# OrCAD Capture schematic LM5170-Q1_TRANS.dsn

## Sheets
1 PAGE1: size E; title: LM5170-Q1 Multiphase Bidirectional Current Controller; rev: 1.0; note: Datasheet: SNVSAQ6B    EVM: NA; note: Synchronous Step Down Converter
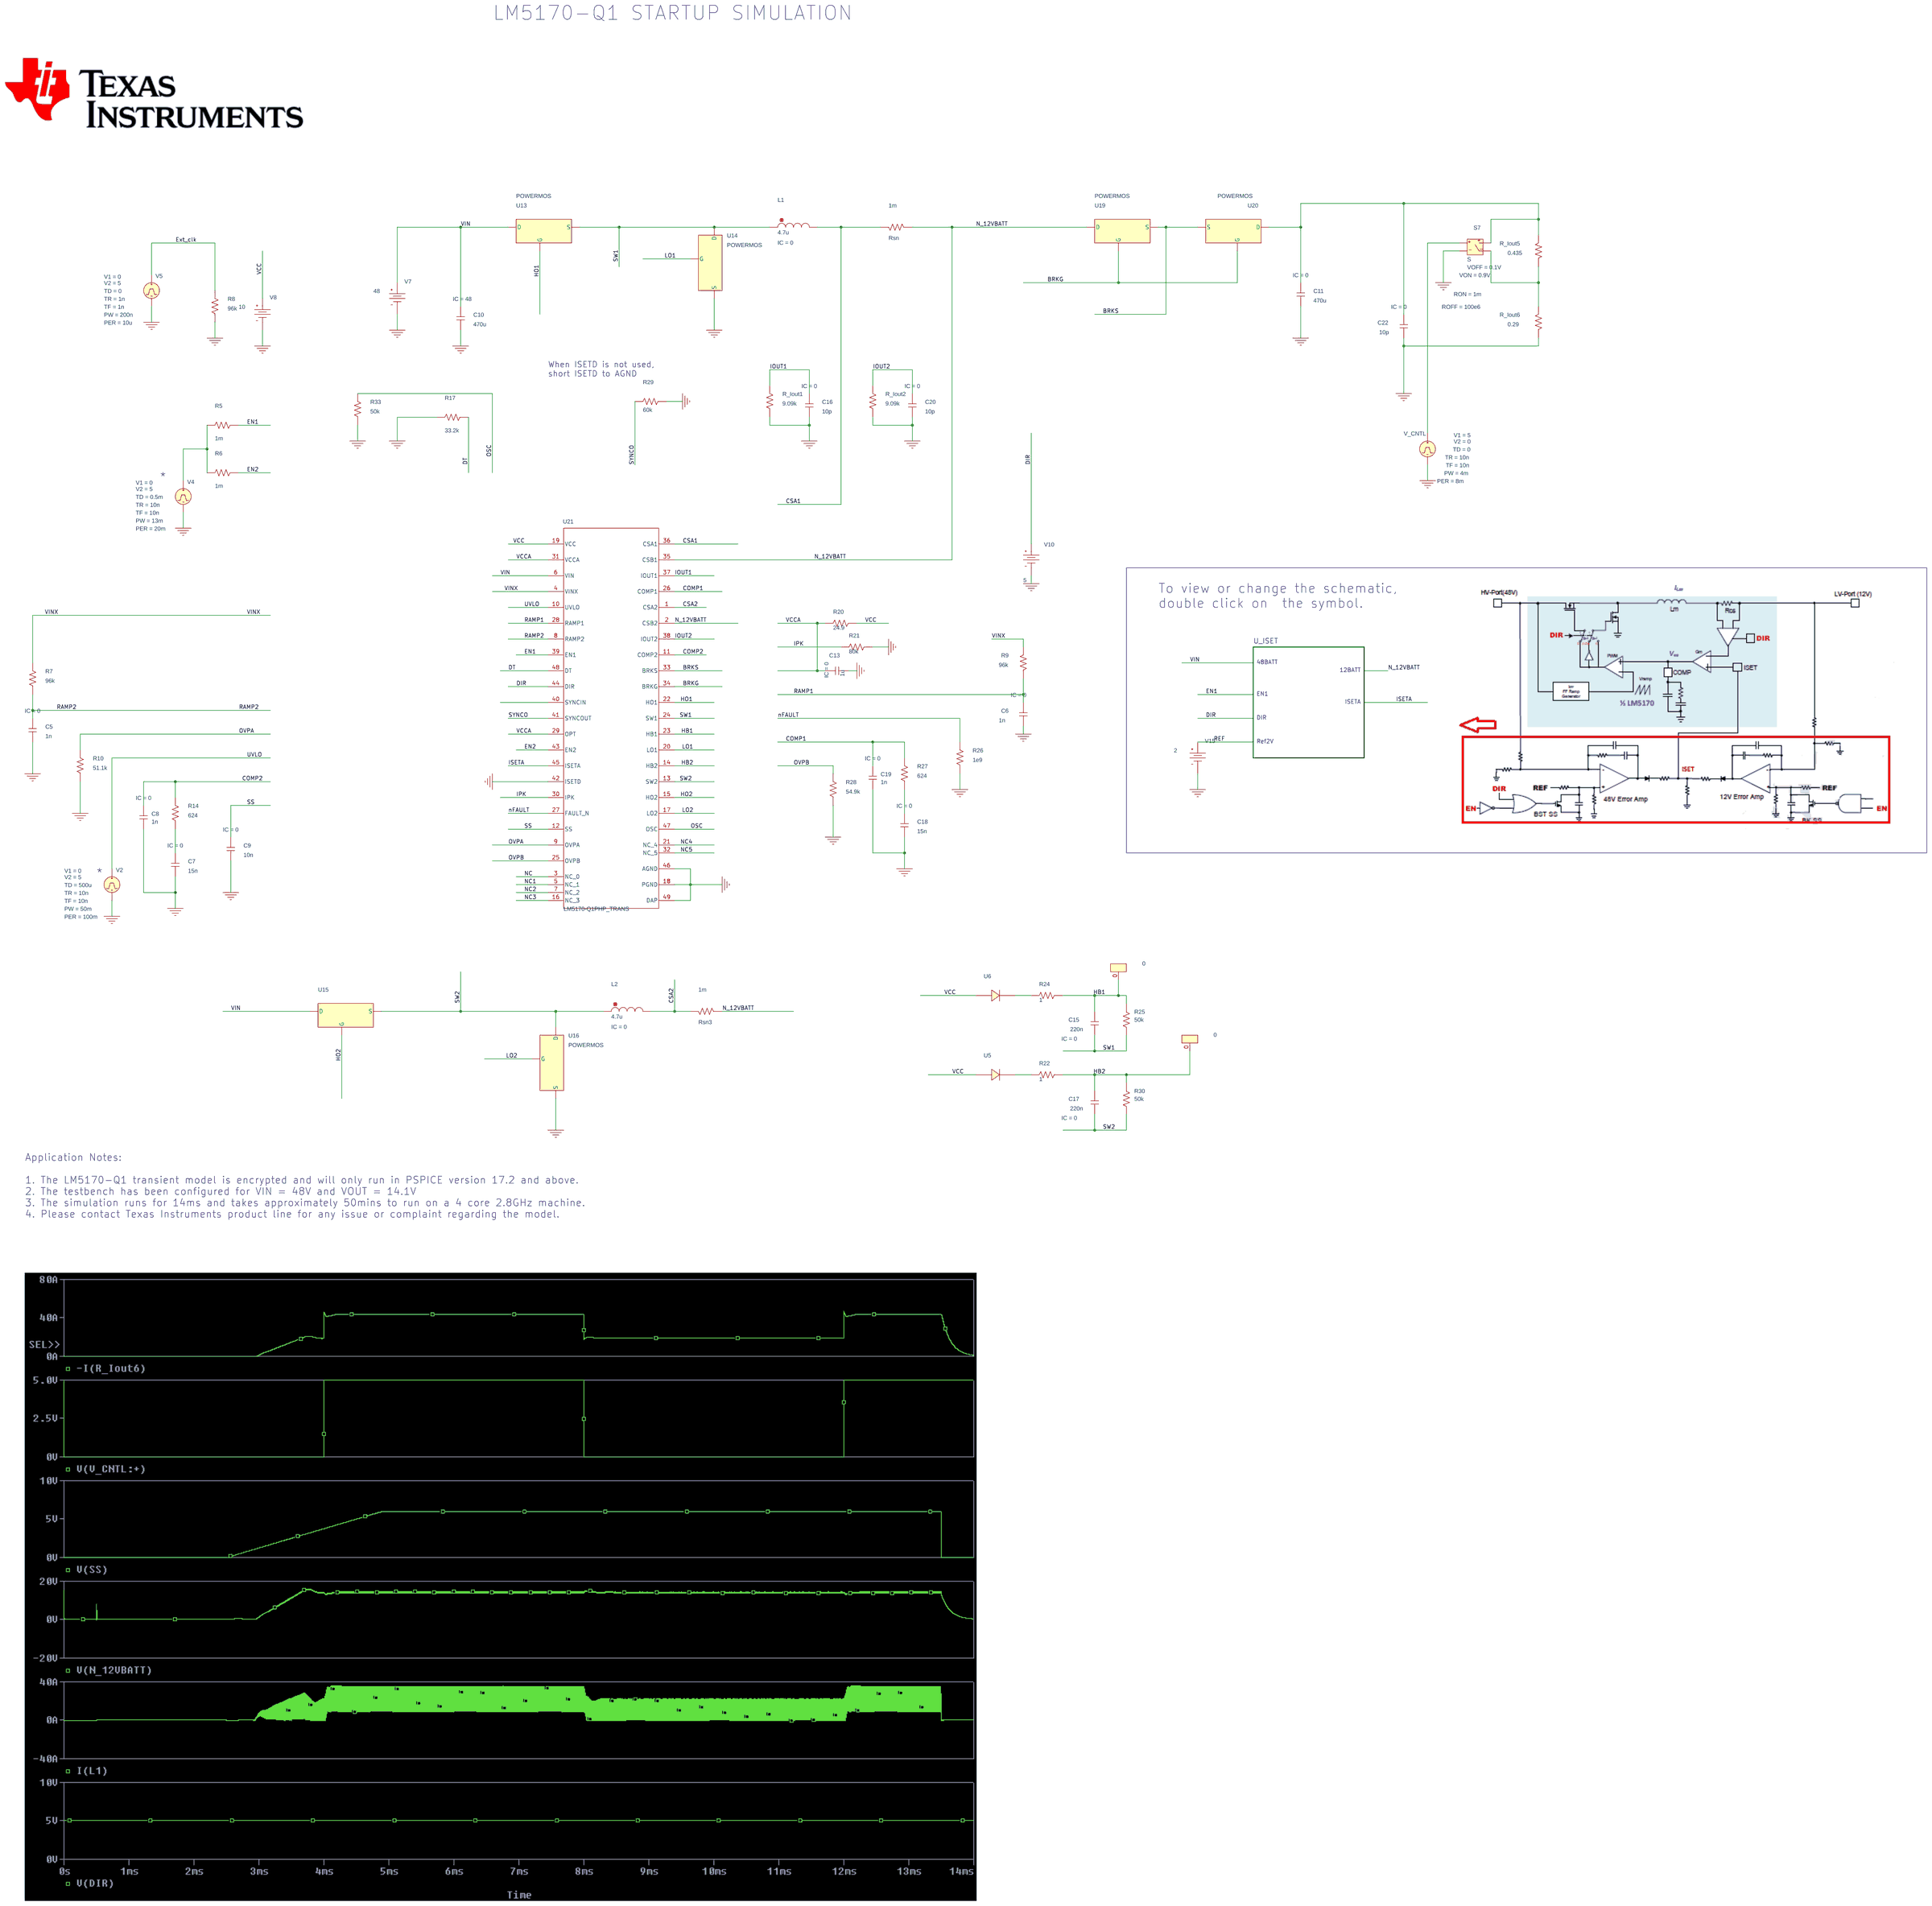
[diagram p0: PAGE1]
2 PAGE1 (2): size Custom; block U_ISET
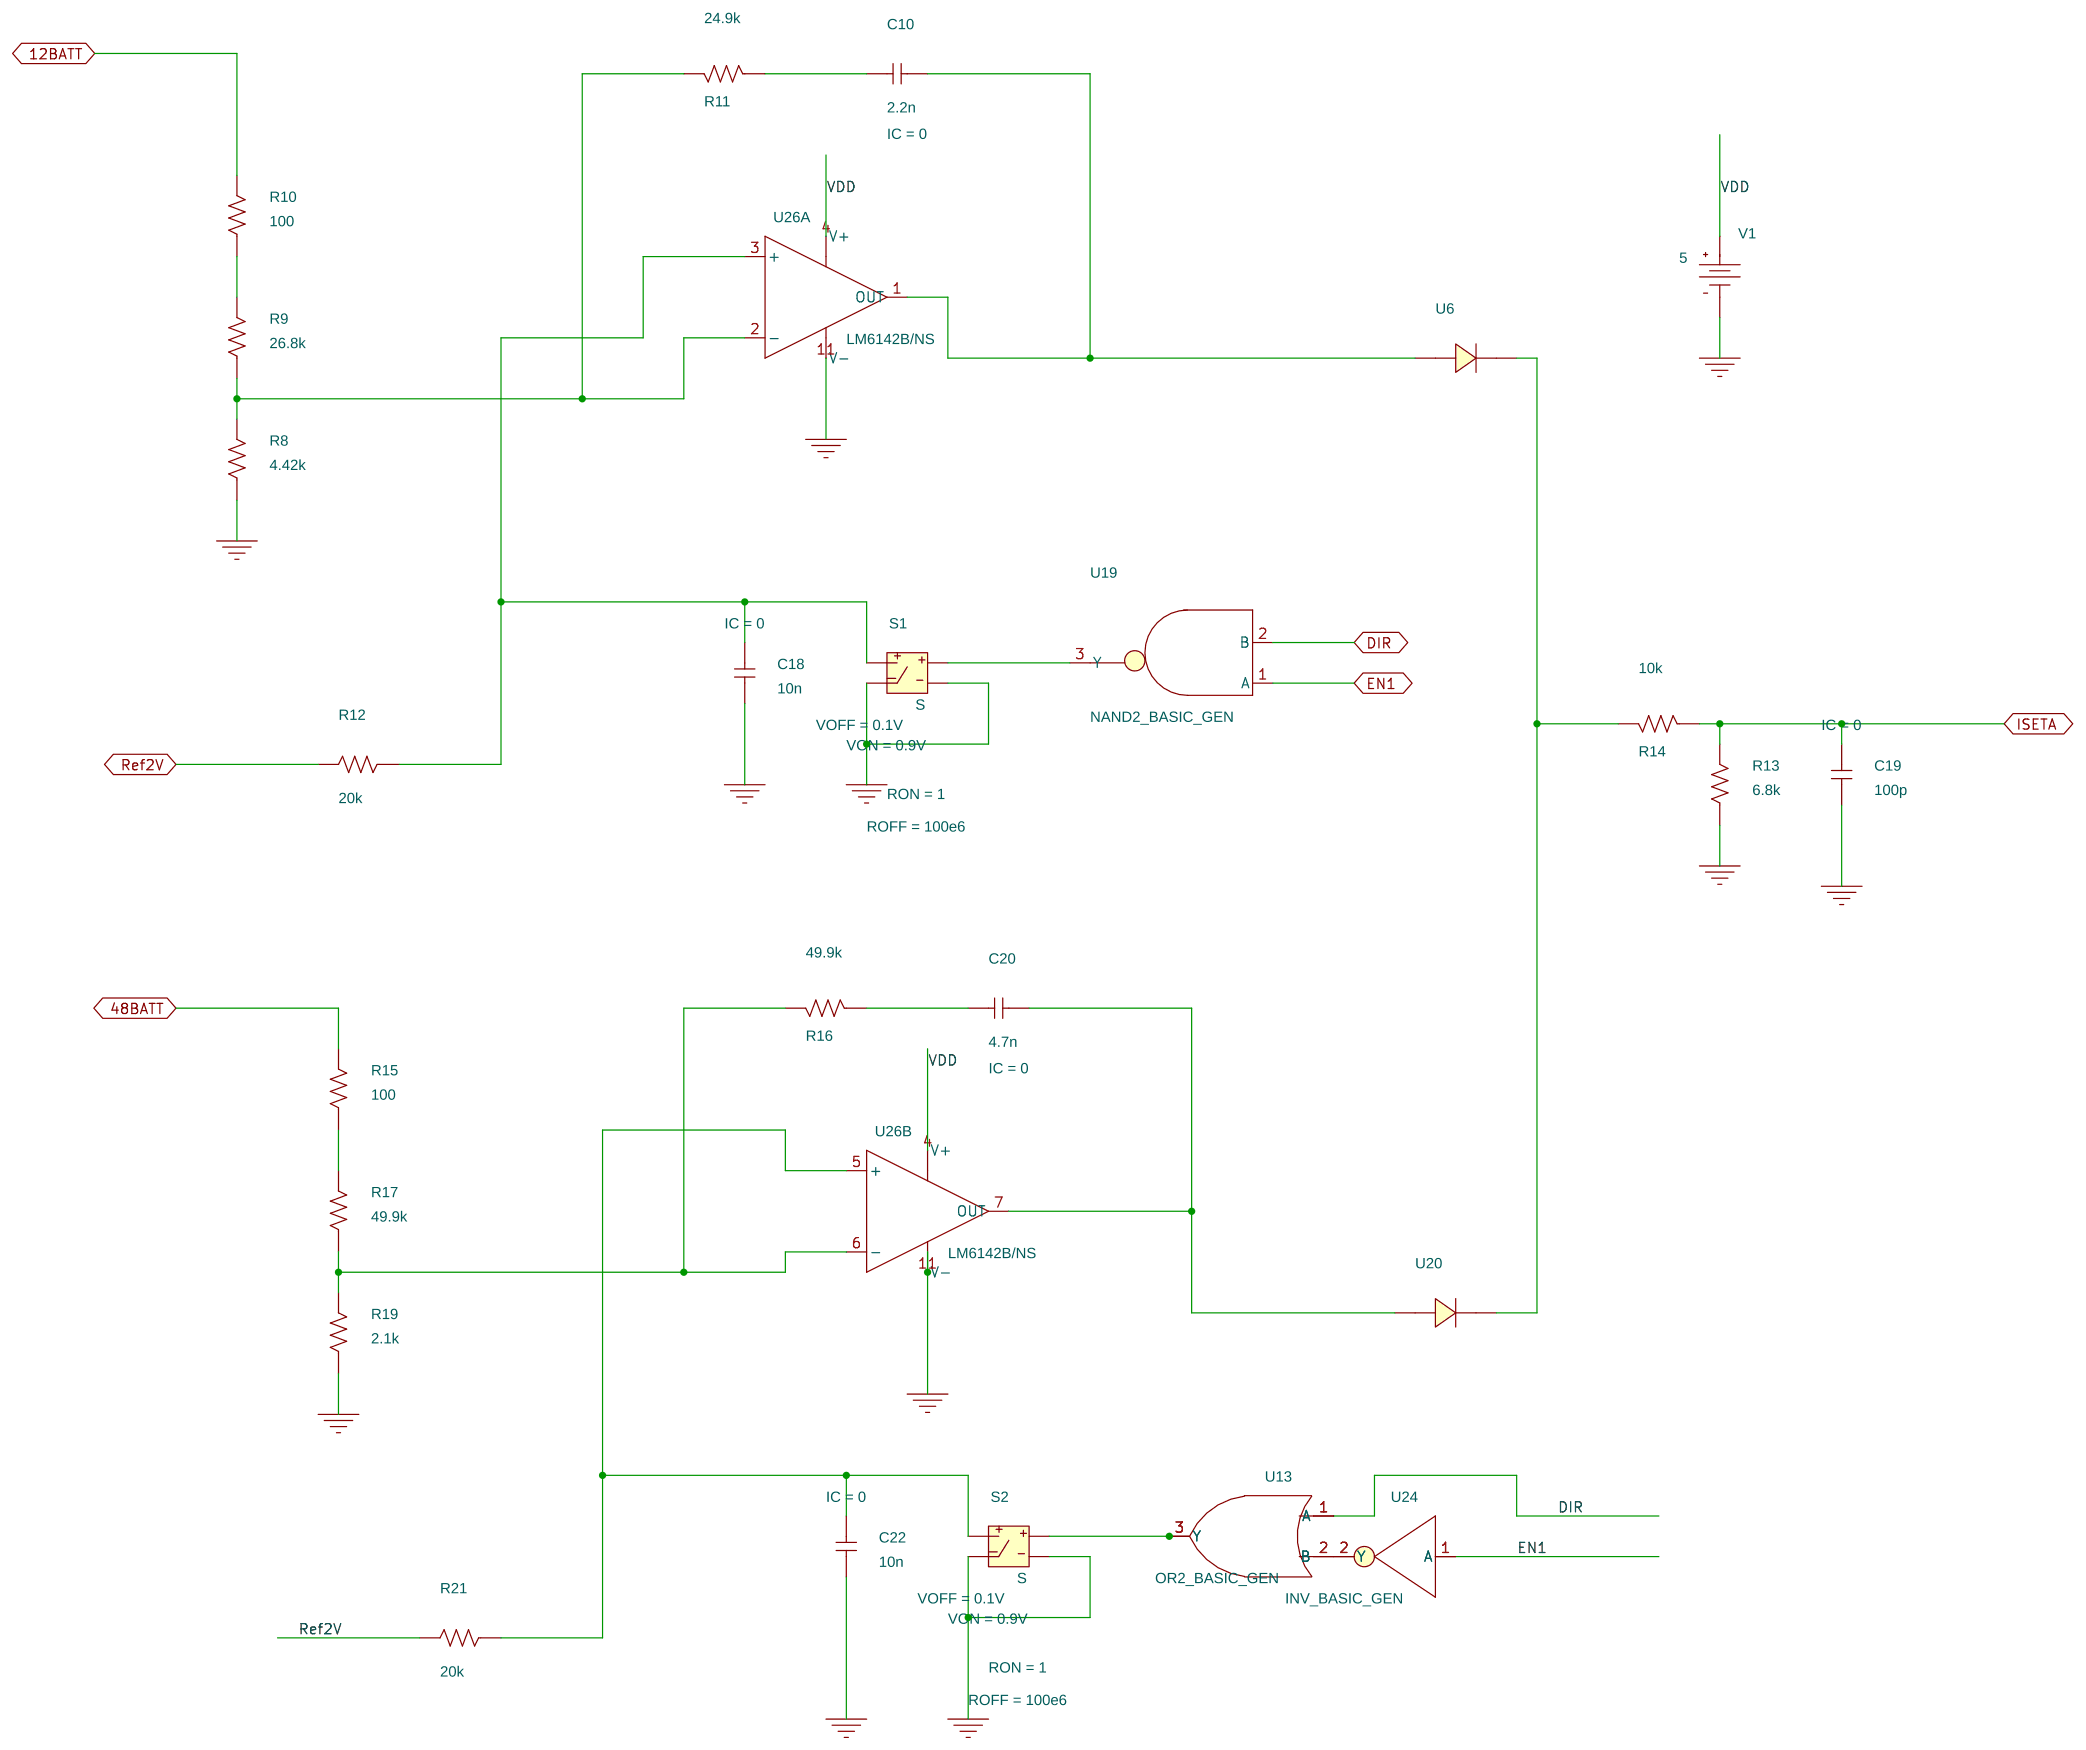
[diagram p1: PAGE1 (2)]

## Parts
sheet PAGE1 (2)
C10#2  2.2n  [RAD/CK05]
C18#2  10n  [RAD/CK05]
C19#2  100p  [RAD/CK05]
C20#2  4.7n  [RAD/CK05]
C22#2  10n  [RAD/CK05]
R8#2  4.42k  [AX/RC05]
R9#2  26.8k  [AX/RC05]
R10#2  100  [AX/RC05]
R11  24.9k  [AX/RC05]
R12  20k  [AX/RC05]
R13  6.8k  [AX/RC05]
R14#2  10k  [AX/RC05]
R15  100  [AX/RC05]
R16  49.9k  [AX/RC05]
R17#2  49.9k  [AX/RC05]
R19  2.1k  [AX/RC05]
R21#2  20k  [AX/RC05]
S1  S
S2  S
U6#2  D_D
U24  INV_BASIC_GEN
U26  LM6142B/NS  [DIP1008W300L450]  (sections A,B)
V1  VDC
sheet PAGE1
C5  1n  [RAD/CK05]
C6  1n  [RAD/CK05]
C7  15n  [RAD/CK05]
C8  1n  [RAD/CK05]
C9  10n  [RAD/CK05]
C10  470u  [RAD/CK05]
C11  470u  [RAD/CK05]
C13  1u  [RAD/CK05]
C15  220n  [RAD/CK05]
C16  10p  [RAD/CK05]
C17  220n  [RAD/CK05]
C18  15n  [RAD/CK05]
C19  1n  [RAD/CK05]
C20  10p  [RAD/CK05]
C22  10p  [RAD/CK05]
IC1  0
IC2  0
L1  4.7u  [DISC/.350x.175/LS.200x.100/.034]
L2  4.7u  [DISC/.350x.175/LS.200x.100/.034]
R5  1m  [AX/RC05]
R6  1m  [AX/RC05]
R7  96k  [AX/RC05]
R8  96k  [AX/RC05]
R9  96k  [AX/RC05]
R10  51.1k  [AX/RC05]
R14  624  [AX/RC05]
R17  33.2k  [AX/RC05]
R20  24.9  [AX/RC05]
R21  80k  [AX/RC05]
R22  1  [AX/RC05]
R24  1  [AX/RC05]
R25  50k  [AX/RC05]
R26  1e9  [AX/RC05]
R27  624  [AX/RC05]
R28  54.9k  [AX/RC05]
R29  60k  [AX/RC05]
R30  50k  [AX/RC05]
R33  50k  [AX/RC05]
R_Iout1  9.09k  [AX/RC05]
R_Iout2  9.09k  [AX/RC05]
R_Iout5  0.435  [AX/RC05]
R_Iout6  0.29  [AX/RC05]
Rsn  1m  [AX/RC05]
Rsn3  1m  [AX/RC05]
S7  S
U5  D_D
U6  D_D
U13  POWERMOS
U14  POWERMOS
U15  POWERMOS
U16  POWERMOS
U19  POWERMOS
U20  POWERMOS
U21  LM5170-Q1PHP_TRANS  [PHP0048D_N]
V2  VPULSE
V4  VPULSE
V5  VPULSE
V7  VDC
V8  VDC
V10  VDC
V15  VDC
V_CNTL  VPULSE

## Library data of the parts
C5-C9 C10#2 C11 C13 C15-C18 C18#2 C19 C19#2 C20 C20#2 C22 C22#2 = C: IC: 0
R5-R8 R8#2 R9 R9#2 R10 R10#2 R11-R14 R14#2 R15-R17 R17#2 R19-R21 R21#2 R22 R24-R30 R33 R_Iout1 R_Iout2 R_Iout5 R_Iout6 Rsn Rsn3 = R
S1 S2 = S: ROFF: 100e6; RON: 1; VOFF: 0.1V; VON: 0.9V
U6 U6#2 = D_D
U24 = INV_BASIC_GEN
U26 = LM6142B_NS
V1 V10 = VDC: DC: 5
C10 = C: IC: 48
IC1 IC2 = IC1
L1 L2 = L: IC: 0
S7 = S: ROFF: 100e6; RON: 1m; VOFF: 0.1V; VON: 0.9V
U5 = D_D_1
U13 = POWERMOS_1_4
U14 = POWERMOS_1_2
U15 = POWERMOS_1_5
U16 = POWERMOS_1_1
U19 = POWERMOS_1
U20 = POWERMOS_1_3
U21 = LM5170-Q1PHP_TRANS
V2 = VPULSE: PER: 100m; PW: 50m; TD: 500u; TF: 10n; TR: 10n; V1: 0; V2: 5
V4 = VPULSE: PER: 20m; PW: 13m; TD: 0.5m; TF: 10n; TR: 10n; V1: 0; V2: 5
V5 = VPULSE: PER: 10u; PW: 200n; TD: 0; TF: 1n; TR: 1n; V1: 0; V2: 5
V7 = VDC: DC: 48
V8 = VDC: DC: 10
V15 = VDC: DC: 2
V_CNTL = VPULSE: PER: 8m; PW: 4m; TD: 0; TF: 10n; TR: 10n; V1: 5; V2: 0

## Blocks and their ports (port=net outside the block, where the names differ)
U_ISET = schematic Iset_driver_block, on sheet PAGE1: 12BATT=N_12VBATT, Ref2V=REF, DIR, EN1, ISETA, 48BATT=VIN

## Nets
U_ISET/VDD: U26.4(V+) V1.0(+)
VCC: R20.1 U5.1 U6.1 U21.19(VCC) V8.0(+)
VCCA: C13.2 R20.2 U21.29(OPT) U21.31(VCCA)
VIN: C10.2 R15.2 U13.D U15.D U21.6(VIN) V7.0(+)
VINX: R7.2 R9.2 U21.4(VINX)
0: C5.1 C6.1 C7.1 C8.1 C9.1 C10.1 C11.1 C13.1 C16.1 C18.1 C18#2.1 C19.1 C19#2.1 C20.1 C22.1 C22#2.1 R8.1 R8#2.1 R10.1 R13.1 R17.2 R19.1 R21.1 R26.1 R28.1 R29.1 R33.1 R_Iout1.1 R_Iout2.1 R_Iout6.1 S1.1(2) S1.3(4) S2.1(2) S2.3(4) S7.1(2) U14.S U16.S U21.18(PGND) U21.42(ISETD) U21.46(AGND) U21.49(DAP) U26.11(V-) V1.1(-) V2.2(-) V4.2(-) V5.2(-) V7.1(-) V8.1(-) V10.1(-) V15.1(-) V_CNTL.2(-)
BRKG: U19.G U20.G U21.34(BRKG)
BRKS: U19.S U20.S U21.33(BRKS)
COMP1: C19.2 R27.2 U21.26(COMP1)
COMP2: C8.2 R14.2 U21.11(COMP2)
CSA1: L1.2 Rsn.2 U21.36(CSA1)
CSA2: L2.2 Rsn3.2 U21.1(CSA2)
DIR: U13.1(A) U19.2(B) U21.44(DIR) V10.0(+)
DT: R17.1 U21.48(DT)
EN1: R5.1 U19.1(A) U21.39(EN1) U24.1(A)
EN2: R6.1 U21.43(EN2)
Ext_clk: R8.2 V5.1(+)
HB1: C15.1 IC1.0(+) R24.1 R25.1 U21.23(HB1)
HB2: C17.1 IC2.0(+) R22.1 R30.1 U21.14(HB2)
HO1: U13.G U21.22(HO1)
HO2: U15.G U21.15(HO2)
IOUT1: C16.2 R_Iout1.2 U21.37(IOUT1)
IOUT2: C20.2 R_Iout2.2 U21.38(IOUT2)
IPK: R21.2 U21.30(IPK)
ISETA: C19#2.2 R13.2 R14#2.1 U21.45(ISETA)
LO1: U14.G U21.20(LO1)
LO2: U16.G U21.17(LO2)
N_12VBATT: R10#2.2 Rsn.1 Rsn3.1 U19.D U21.2(CSB2) U21.35(CSB1)
NC: U21.3(NC_0)
NC1: U21.5(NC_1)
NC2: U21.7(NC_2)
NC3: U21.16(NC_3)
NC4: U21.21(NC_4)
NC5: U21.32(NC_5)
nFAULT: R26.2 U21.27(FAULT_N)
OSC: R33.2 U21.47(OSC)
OVPA: R10.2 U21.9(OVPA)
OVPB: R28.2 U21.25(OVPB)
RAMP1: C6.2 R9.1 U21.28(RAMP1)
RAMP2: C5.2 R7.1 U21.8(RAMP2)
REF: R12.2 R21#2.2 V15.0(+)
SS: C9.2 U21.12(SS)
SW1: C15.2 L1.1 R25.2 U13.S U14.D U21.24(SW1)
SW2: C17.2 L2.1 R30.2 U15.S U16.D U21.13(SW2)
SYNCO: R29.2 U21.41(SYNCOUT)
UVLO: U21.10(UVLO) V2.1(+)
N68559: C11.2 C22.2 R_Iout5.2 S7.2(3) U20.D
N68779: S7.0(1) V_CNTL.1(+)
N68849: R_Iout5.1 R_Iout6.2 S7.3(4)
N69469: R5.2 R6.2 V4.1(+)
N71013: C7.2 R14.1
N71025: C18.2 R27.1
N71213: R24.2 U6.2
N71543: R22.2 U5.2
N16778051: U13.2(B) U24.2(Y)
U_ISET/N00132: R8#2.2 R9#2.1 R11.2 U26.2(-)
U_ISET/N00179: R9#2.2 R10#2.1
U_ISET/N00294: C10#2.2 R11.1
U_ISET/N00319: C10#2.1 U6#2.1 U26.1(OUT)
U_ISET/N00376: C18#2.2 R12.1 S1.2(3) U26.3(+)
U_ISET/N06510: S1.0(1) U19.3(Y)
U_ISET/N16775260: R16.2 R17#2.1 R19.2 U26.6(-)
U_ISET/N16775268: C20#2.2 R16.1
U_ISET/N16775272: C20#2.1 U20.1 U26.7(OUT)
U_ISET/N16775280: R15.1 R17#2.2
U_ISET/N16775306: C22#2.2 R21#2.1 S2.2(3) U26.5(+)
U_ISET/N16775612: S2.0(1) U13.3(Y)
U_ISET/N16775823: R14#2.2 U6#2.2 U20.2

Not connected (* = marked no-connect by the designer): U21 40(SYNCIN)

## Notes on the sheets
sheet 1
- LM5170-Q1 STARTUP SIMULATION
- When ISETD is not used,
  short ISETD to AGND
- *
- To view or change the schematic,
  double click on  the symbol.
- *
- Application Notes:
  1. The LM5170-Q1 transient model is encrypted and will only run in PSPICE version 17.2 and above.
  2. The testbench has been configured for VIN = 48V and VOUT = 14.1V
  3. The simulation runs for 14ms and takes approximately 50mins to run on a 4 core 2.8GHz machine.
  4. Please contact Texas Instruments product line for any issue or complaint regarding the model.
